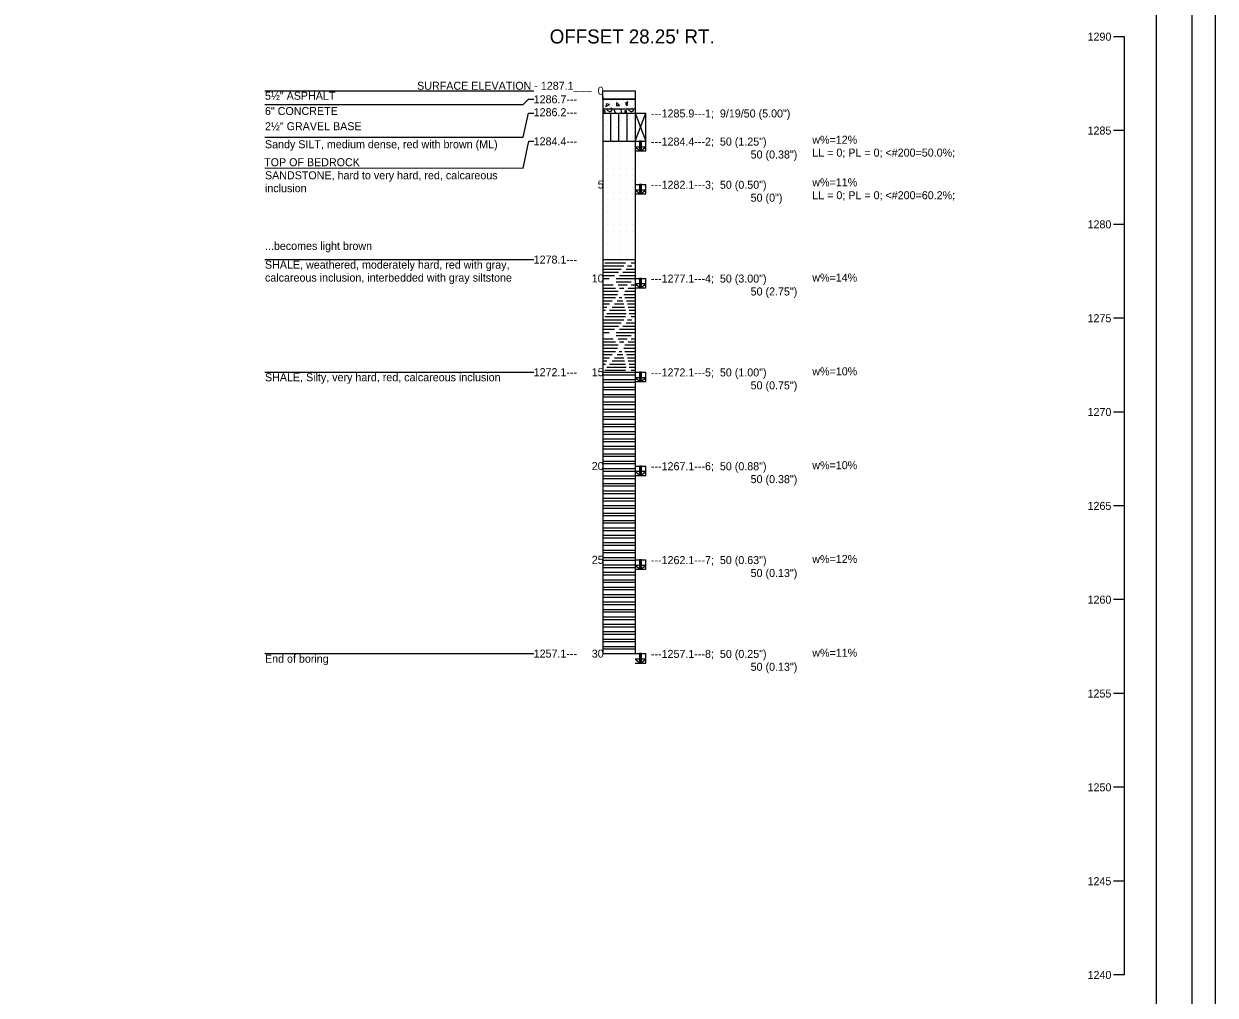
# Model space of a CAD drawing. Extents: x -6 to 173, y 24 to 64.
# Drawn here: x 107.52 to 125.98, y 35.65 to 50.69 of the extents above; entities that cross this region are included whole.
import ezdxf

# ---------------------------------------------------------------- set-up
doc = ezdxf.new("R2010")
doc.units = 0
for name, color, linetype in [('SHT_Plot_Shape_Full', 7, 'Continuous'), ('SHT_Plot_Shape_Half', 7, 'Continuous'), ('SHT_Sheet_Border', 7, 'Continuous')]:
    doc.layers.add(name, color=color, linetype=linetype)

# ---------------------------------------------------------------- blocks, each defined once
blk = doc.blocks.new('POINT_DISPLAY')
blk.add_line((0, 0), (0, 0))

msp = doc.modelspace()

# ---------------------------------------------------------------- linework, layer by layer
msp.add_line((124.573, 35.958), (124.573, 50.493))
for points in [[(124.573, 50.493), (124.406, 50.493)], [(111.26, 49.656), (115.427, 49.656)], [(111.26, 49.44), (115.26, 49.44), (115.344, 49.523), (115.427, 49.523)], [(116.493, 49.563), (116.493, 40.936)], [(116.493, 49.523), (116.993, 49.523)], [(116.753, 49.428), (116.706, 49.474), (116.706, 49.428), (116.753, 49.428)], [(116.87, 49.42), (116.882, 49.486), (116.843, 49.459), (116.87, 49.42)], [(116.993, 49.523), (116.993, 40.936)], [(111.26, 48.935), (115.26, 48.935), (115.344, 49.308), (115.427, 49.308)], [(116.493, 49.377), (116.993, 49.377)], [(116.493, 49.308), (116.993, 49.308)], [(116.506, 49.347), (116.496, 49.337), (116.499, 49.327), (116.504, 49.314), (116.515, 49.312), (116.528, 49.322), (116.528, 49.336), (116.519, 49.351), (116.506, 49.347)], [(116.539, 49.409), (116.597, 49.442), (116.551, 49.454), (116.539, 49.409)], [(116.629, 49.377), (116.629, 49.346), (116.624, 49.338), (116.609, 49.33), (116.594, 49.331), (116.584, 49.338), (116.572, 49.346), (116.561, 49.353), (116.554, 49.367), (116.554, 49.377)], [(116.626, 49.389), (116.614, 49.377), (116.626, 49.377), (116.626, 49.389)], [(116.618, 48.872), (116.618, 49.308)], [(116.7, 49.308), (116.693, 49.313), (116.681, 49.332), (116.675, 49.352), (116.674, 49.352), (116.677, 49.377)], [(116.743, 48.872), (116.743, 49.308)], [(116.769, 49.377), (116.774, 49.367), (116.774, 49.356), (116.775, 49.342), (116.778, 49.338), (116.782, 49.331), (116.777, 49.311), (116.772, 49.308)], [(116.839, 49.347), (116.829, 49.337), (116.833, 49.327), (116.838, 49.314), (116.849, 49.312), (116.861, 49.322), (116.861, 49.336), (116.853, 49.351), (116.839, 49.347)], [(116.868, 48.872), (116.868, 49.308)], [(116.962, 49.377), (116.963, 49.346), (116.957, 49.338), (116.942, 49.33), (116.928, 49.331), (116.917, 49.338), (116.905, 49.346), (116.894, 49.353), (116.888, 49.367), (116.888, 49.377)], [(116.954, 49.381), (116.94, 49.377), (116.951, 49.377), (116.954, 49.381)], [(116.993, 49.308), (117.159, 48.872)], [(116.993, 48.872), (117.159, 49.308)], [(116.993, 49.308), (117.159, 49.308)], [(117.159, 48.872), (117.159, 49.308)], [(124.573, 49.039), (124.406, 49.039)], [(111.26, 48.46), (115.26, 48.456), (115.345, 48.872), (115.427, 48.872)], [(116.493, 48.872), (116.993, 48.872)], [(116.993, 48.872), (117.159, 48.872)], [(116.993, 48.872), (117.159, 48.872)], [(116.993, 48.726), (117.159, 48.726)], [(117.159, 48.726), (117.159, 48.872)], [(116.993, 48.203), (117.159, 48.203)], [(117.159, 48.058), (117.159, 48.203)], [(116.993, 48.058), (117.159, 48.058)], [(124.573, 47.586), (124.406, 47.586)], [(111.26, 47.04), (115.427, 47.04)], [(116.493, 47.04), (116.993, 47.04)], [(116.493, 46.942), (116.819, 46.942)], [(116.493, 46.893), (116.779, 46.893)], [(116.526, 46.992), (116.844, 46.992)], [(116.558, 47.04), (116.853, 47.04)], [(116.853, 46.893), (116.983, 46.893)], [(116.876, 46.942), (116.943, 46.942)], [(116.901, 47.04), (116.993, 47.04)], [(116.934, 46.992), (116.993, 46.992)], [(116.493, 46.843), (116.738, 46.843)], [(116.493, 46.795), (116.673, 46.795)], [(116.493, 46.747), (116.591, 46.747)], [(116.698, 46.747), (116.993, 46.747)], [(116.698, 46.697), (116.934, 46.697)], [(116.754, 46.795), (116.993, 46.795)], [(116.803, 46.843), (116.993, 46.843)], [(116.993, 46.749), (117.159, 46.749)], [(117.159, 46.604), (117.159, 46.749)], [(116.493, 46.648), (116.656, 46.648)], [(116.493, 46.598), (116.689, 46.598)], [(116.493, 46.55), (116.729, 46.55)], [(116.729, 46.648), (116.868, 46.648)], [(116.754, 46.598), (116.819, 46.598)], [(116.836, 46.55), (116.993, 46.55)], [(116.884, 46.598), (116.993, 46.598)], [(116.934, 46.648), (116.993, 46.648)], [(116.993, 46.604), (117.159, 46.604)], [(116.493, 46.5), (116.721, 46.5)], [(116.493, 46.452), (116.689, 46.452)], [(116.493, 46.403), (116.639, 46.403)], [(116.493, 46.353), (116.599, 46.353)], [(116.673, 46.353), (116.819, 46.353)], [(116.713, 46.403), (116.803, 46.403)], [(116.746, 46.452), (116.786, 46.452)], [(116.819, 46.5), (116.993, 46.5)], [(116.836, 46.452), (116.993, 46.452)], [(116.861, 46.403), (116.993, 46.403)], [(116.876, 46.353), (116.993, 46.353)], [(116.493, 46.305), (116.558, 46.305)], [(116.493, 46.255), (116.534, 46.255)], [(116.526, 46.158), (116.844, 46.158)], [(116.558, 46.207), (116.853, 46.207)], [(116.599, 46.255), (116.844, 46.255)], [(116.639, 46.305), (116.828, 46.305)], [(116.884, 46.305), (116.993, 46.305)], [(116.901, 46.255), (116.993, 46.255)], [(116.901, 46.207), (116.993, 46.207)], [(116.934, 46.158), (116.993, 46.158)], [(116.493, 46.108), (116.819, 46.108)], [(116.493, 46.06), (116.779, 46.06)], [(116.493, 46.01), (116.738, 46.01)], [(116.493, 45.962), (116.673, 45.962)], [(116.754, 45.962), (116.993, 45.962)], [(116.803, 46.01), (116.993, 46.01)], [(116.853, 46.06), (116.983, 46.06)], [(116.876, 46.108), (116.943, 46.108)], [(124.573, 46.132), (124.406, 46.132)], [(116.493, 45.913), (116.591, 45.913)], [(116.493, 45.815), (116.656, 45.815)], [(116.698, 45.913), (116.993, 45.913)], [(116.698, 45.863), (116.934, 45.863)], [(116.729, 45.815), (116.868, 45.815)], [(116.934, 45.815), (116.993, 45.815)], [(116.493, 45.765), (116.689, 45.765)], [(116.493, 45.717), (116.729, 45.717)], [(116.493, 45.667), (116.721, 45.667)], [(116.493, 45.618), (116.689, 45.618)], [(116.746, 45.618), (116.786, 45.618)], [(116.754, 45.765), (116.819, 45.765)], [(116.819, 45.667), (116.993, 45.667)], [(116.836, 45.717), (116.993, 45.717)], [(116.836, 45.618), (116.993, 45.618)], [(116.884, 45.765), (116.993, 45.765)], [(116.493, 45.57), (116.639, 45.57)], [(116.493, 45.52), (116.599, 45.52)], [(116.493, 45.472), (116.558, 45.472)], [(116.493, 45.422), (116.534, 45.422)], [(116.599, 45.422), (116.844, 45.422)], [(116.639, 45.472), (116.828, 45.472)], [(116.673, 45.52), (116.819, 45.52)], [(116.713, 45.57), (116.803, 45.57)], [(116.861, 45.57), (116.993, 45.57)], [(116.876, 45.52), (116.993, 45.52)], [(116.884, 45.472), (116.993, 45.472)], [(116.901, 45.422), (116.993, 45.422)], [(111.26, 45.296), (115.427, 45.296)], [(116.493, 45.296), (116.993, 45.296)], [(116.493, 45.296), (116.993, 45.296)], [(116.493, 45.257), (116.993, 45.257)], [(116.526, 45.325), (116.844, 45.325)], [(116.558, 45.373), (116.853, 45.373)], [(116.901, 45.373), (116.993, 45.373)], [(116.934, 45.325), (116.993, 45.325)], [(116.993, 45.296), (117.159, 45.296)], [(117.159, 45.151), (117.159, 45.296)], [(116.493, 45.181), (116.993, 45.181)], [(116.493, 45.142), (116.993, 45.142)], [(116.493, 45.066), (116.993, 45.066)], [(116.993, 45.151), (117.159, 45.151)], [(116.493, 45.027), (116.993, 45.027)], [(116.493, 44.951), (116.993, 44.951)], [(116.493, 44.912), (116.993, 44.912)], [(116.493, 44.837), (116.993, 44.837)], [(116.493, 44.797), (116.993, 44.797)], [(116.493, 44.722), (116.993, 44.722)], [(116.493, 44.682), (116.993, 44.682)], [(124.573, 44.679), (124.406, 44.679)], [(116.493, 44.607), (116.993, 44.607)], [(116.493, 44.568), (116.993, 44.568)], [(116.493, 44.492), (116.993, 44.492)], [(116.493, 44.453), (116.993, 44.453)], [(116.493, 44.377), (116.993, 44.377)], [(116.493, 44.338), (116.993, 44.338)], [(116.493, 44.263), (116.993, 44.263)], [(116.493, 44.223), (116.993, 44.223)], [(116.493, 44.148), (116.993, 44.148)], [(116.493, 44.108), (116.993, 44.108)], [(116.493, 44.033), (116.993, 44.033)], [(116.493, 43.993), (116.993, 43.993)], [(116.493, 43.918), (116.993, 43.918)], [(116.493, 43.879), (116.993, 43.879)], [(116.493, 43.803), (116.993, 43.803)], [(116.493, 43.764), (116.993, 43.764)], [(116.993, 43.842), (117.159, 43.842)], [(117.159, 43.697), (117.159, 43.842)], [(116.493, 43.688), (116.993, 43.688)], [(116.493, 43.649), (116.993, 43.649)], [(116.493, 43.574), (116.993, 43.574)], [(116.993, 43.697), (117.159, 43.697)], [(116.493, 43.534), (116.993, 43.534)], [(116.493, 43.459), (116.993, 43.459)], [(116.493, 43.419), (116.993, 43.419)], [(116.493, 43.344), (116.993, 43.344)], [(116.493, 43.305), (116.993, 43.305)], [(116.493, 43.229), (116.993, 43.229)], [(116.493, 43.19), (116.993, 43.19)], [(124.573, 43.225), (124.406, 43.225)], [(116.493, 43.114), (116.993, 43.114)], [(116.493, 43.075), (116.993, 43.075)], [(116.493, 42.999), (116.993, 42.999)], [(116.493, 42.96), (116.993, 42.96)], [(116.493, 42.885), (116.993, 42.885)], [(116.493, 42.845), (116.993, 42.845)], [(116.493, 42.77), (116.993, 42.77)], [(116.493, 42.73), (116.993, 42.73)], [(116.493, 42.655), (116.993, 42.655)], [(116.493, 42.616), (116.993, 42.616)], [(116.493, 42.54), (116.993, 42.54)], [(116.493, 42.501), (116.993, 42.501)], [(116.493, 42.425), (116.993, 42.425)], [(116.493, 42.386), (116.993, 42.386)], [(116.493, 42.31), (116.993, 42.31)], [(116.493, 42.271), (116.993, 42.271)], [(116.993, 42.389), (117.159, 42.389)], [(117.159, 42.244), (117.159, 42.389)], [(116.493, 42.196), (116.993, 42.196)], [(116.493, 42.156), (116.993, 42.156)], [(116.493, 42.081), (116.993, 42.081)], [(116.993, 42.244), (117.159, 42.244)], [(116.493, 42.041), (116.993, 42.041)], [(116.493, 41.966), (116.993, 41.966)], [(116.493, 41.927), (116.993, 41.927)], [(116.493, 41.851), (116.993, 41.851)], [(116.493, 41.812), (116.993, 41.812)], [(116.493, 41.736), (116.993, 41.736)], [(124.573, 41.772), (124.406, 41.772)], [(116.493, 41.697), (116.993, 41.697)], [(116.493, 41.621), (116.993, 41.621)], [(116.493, 41.582), (116.993, 41.582)], [(116.493, 41.507), (116.993, 41.507)], [(116.493, 41.467), (116.993, 41.467)], [(116.493, 41.392), (116.993, 41.392)], [(116.493, 41.352), (116.993, 41.352)], [(116.493, 41.277), (116.993, 41.277)], [(116.493, 41.238), (116.993, 41.238)], [(116.493, 41.162), (116.993, 41.162)], [(116.493, 41.123), (116.993, 41.123)], [(116.493, 41.047), (116.993, 41.047)], [(116.493, 41.008), (116.993, 41.008)], [(111.26, 40.936), (115.427, 40.936)], [(116.493, 40.936), (116.993, 40.936)], [(116.993, 40.936), (117.159, 40.936)], [(116.993, 40.79), (117.159, 40.79)], [(117.159, 40.79), (117.159, 40.936)], [(124.573, 40.318), (124.406, 40.318)], [(124.573, 38.865), (124.406, 38.865)], [(124.573, 37.411), (124.406, 37.411)], [(124.573, 35.958), (124.406, 35.958)]]:
    msp.add_lwpolyline(points)
for points in [[(116.493, 49.523), (116.493, 49.656), (116.993, 49.656), (116.993, 49.523)], [(117.059, 48.784), (116.993, 48.784), (117.076, 48.726), (117.059, 48.784)], [(117.059, 48.784), (117.093, 48.784), (117.093, 48.872), (117.059, 48.784)], [(117.059, 48.784), (117.093, 48.872), (117.059, 48.872), (117.059, 48.784)], [(117.059, 48.784), (117.076, 48.726), (117.093, 48.784), (117.059, 48.784)], [(117.076, 48.726), (117.159, 48.784), (117.093, 48.784), (117.076, 48.726)], [(117.059, 48.116), (117.093, 48.116), (117.093, 48.203), (117.059, 48.116)], [(117.059, 48.116), (117.093, 48.203), (117.059, 48.203), (117.059, 48.116)], [(117.059, 48.116), (116.993, 48.116), (117.076, 48.058), (117.059, 48.116)], [(117.059, 48.116), (117.076, 48.058), (117.093, 48.116), (117.059, 48.116)], [(117.076, 48.058), (117.159, 48.116), (117.093, 48.116), (117.076, 48.058)], [(117.059, 46.662), (117.093, 46.662), (117.093, 46.749), (117.059, 46.662)], [(117.059, 46.662), (117.093, 46.749), (117.059, 46.749), (117.059, 46.662)], [(117.059, 46.662), (116.993, 46.662), (117.076, 46.604), (117.059, 46.662)], [(117.059, 46.662), (117.076, 46.604), (117.093, 46.662), (117.059, 46.662)], [(117.076, 46.604), (117.159, 46.662), (117.093, 46.662), (117.076, 46.604)], [(117.059, 45.209), (117.093, 45.209), (117.093, 45.296), (117.059, 45.209)], [(117.059, 45.209), (117.093, 45.296), (117.059, 45.296), (117.059, 45.209)], [(117.059, 45.209), (116.993, 45.209), (117.076, 45.151), (117.059, 45.209)], [(117.059, 45.209), (117.076, 45.151), (117.093, 45.209), (117.059, 45.209)], [(117.076, 45.151), (117.159, 45.209), (117.093, 45.209), (117.076, 45.151)], [(117.059, 43.755), (116.993, 43.755), (117.076, 43.697), (117.059, 43.755)], [(117.059, 43.755), (117.093, 43.755), (117.093, 43.842), (117.059, 43.755)], [(117.059, 43.755), (117.093, 43.842), (117.059, 43.842), (117.059, 43.755)], [(117.059, 43.755), (117.076, 43.697), (117.093, 43.755), (117.059, 43.755)], [(117.076, 43.697), (117.159, 43.755), (117.093, 43.755), (117.076, 43.697)], [(117.059, 42.302), (116.993, 42.302), (117.076, 42.244), (117.059, 42.302)], [(117.059, 42.302), (117.093, 42.302), (117.093, 42.389), (117.059, 42.302)], [(117.059, 42.302), (117.093, 42.389), (117.059, 42.389), (117.059, 42.302)], [(117.059, 42.302), (117.076, 42.244), (117.093, 42.302), (117.059, 42.302)], [(117.076, 42.244), (117.159, 42.302), (117.093, 42.302), (117.076, 42.244)], [(117.059, 40.848), (116.993, 40.848), (117.076, 40.79), (117.059, 40.848)], [(117.059, 40.848), (117.093, 40.848), (117.093, 40.936), (117.059, 40.848)], [(117.059, 40.848), (117.093, 40.936), (117.059, 40.936), (117.059, 40.848)], [(117.059, 40.848), (117.076, 40.79), (117.093, 40.848), (117.059, 40.848)], [(117.076, 40.79), (117.159, 40.848), (117.093, 40.848), (117.076, 40.79)]]:
    msp.add_lwpolyline(points, close=True)
at = {"layer": 'SHT_Plot_Shape_Full'}
msp.add_lwpolyline([(89.979, 53.971), (125.979, 53.971), (125.979, 29.971), (89.979, 29.971)], close=True, dxfattribs=at)
at = {"layer": 'SHT_Plot_Shape_Half'}
msp.add_lwpolyline([(91.616, 53.146), (125.616, 53.146), (125.616, 31.146), (91.616, 31.146)], close=True, dxfattribs=at)
at = {"layer": 'SHT_Sheet_Border'}
msp.add_lwpolyline([(93.566, 52.646), (125.066, 52.646), (125.066, 31.646), (93.566, 31.646)], close=True, dxfattribs=at)

# ---------------------------------------------------------------- block references
at = {"xscale": 0.01, "yscale": 0.01}
for p in [(116.496, 49.481), (116.512, 49.514), (116.529, 49.464), (116.546, 49.498), (116.596, 49.514), (116.607, 49.483), (116.629, 49.464), (116.646, 49.498), (116.679, 49.464), (116.706, 49.506), (116.729, 49.481), (116.762, 49.514), (116.796, 49.464), (116.812, 49.498), (116.829, 49.481), (116.846, 49.514), (116.862, 49.464), (116.879, 49.498), (116.929, 49.514), (116.94, 49.483), (116.962, 49.464), (116.979, 49.498), (116.512, 49.431), (116.529, 49.398), (116.532, 49.291), (116.562, 49.448), (116.562, 49.381), (116.596, 49.414), (116.637, 49.427), (116.646, 49.398), (116.699, 49.291), (116.705, 49.389), (116.712, 49.431), (116.75, 49.412), (116.762, 49.448), (116.762, 49.381), (116.79, 49.41), (116.812, 49.381), (116.823, 49.414), (116.846, 49.431), (116.862, 49.398), (116.896, 49.448), (116.896, 49.381), (116.918, 49.274), (116.929, 49.414), (116.971, 49.427), (116.979, 49.398), (116.499, 49.224), (116.532, 49.124), (116.565, 49.191), (116.599, 49.258), (116.632, 49.158), (116.699, 49.091), (116.722, 49.227), (116.765, 49.191), (116.782, 49.115), (116.799, 49.258), (116.865, 49.191), (116.932, 49.124), (116.965, 49.224), (116.564, 49.048), (116.564, 48.949), (116.662, 49.048), (116.662, 48.949), (116.761, 49.048), (116.761, 48.949), (116.859, 49.048), (116.859, 48.949), (116.958, 49.048), (116.958, 48.949), (116.564, 48.851), (116.564, 48.753), (116.662, 48.851), (116.662, 48.753), (116.761, 48.851), (116.761, 48.753), (116.859, 48.851), (116.859, 48.753), (116.958, 48.851), (116.958, 48.753), (116.564, 48.654), (116.564, 48.556), (116.662, 48.654), (116.662, 48.556), (116.761, 48.654), (116.761, 48.556), (116.859, 48.654), (116.859, 48.556), (116.958, 48.654), (116.958, 48.556), (116.564, 48.457), (116.564, 48.359), (116.662, 48.457), (116.662, 48.359), (116.761, 48.457), (116.761, 48.359), (116.859, 48.457), (116.859, 48.359), (116.958, 48.457), (116.958, 48.359), (116.564, 48.26), (116.662, 48.26), (116.761, 48.26), (116.859, 48.26), (116.958, 48.26), (116.564, 48.162), (116.564, 48.064), (116.662, 48.162), (116.662, 48.064), (116.761, 48.162), (116.761, 48.064), (116.859, 48.162), (116.859, 48.064), (116.958, 48.162), (116.958, 48.064), (116.564, 47.965), (116.564, 47.867), (116.662, 47.965), (116.662, 47.867), (116.761, 47.965), (116.761, 47.867), (116.859, 47.965), (116.859, 47.867), (116.958, 47.965), (116.958, 47.867), (116.564, 47.768), (116.564, 47.67), (116.662, 47.768), (116.662, 47.67), (116.761, 47.768), (116.761, 47.67), (116.859, 47.768), (116.859, 47.67), (116.958, 47.768), (116.958, 47.67), (116.564, 47.571), (116.564, 47.473), (116.662, 47.571), (116.662, 47.473), (116.761, 47.571), (116.761, 47.473), (116.859, 47.571), (116.859, 47.473), (116.958, 47.571), (116.958, 47.473), (116.564, 47.375), (116.564, 47.276), (116.662, 47.375), (116.662, 47.276), (116.761, 47.375), (116.761, 47.276), (116.859, 47.375), (116.859, 47.276), (116.958, 47.375), (116.958, 47.276), (116.564, 47.178), (116.564, 47.079), (116.662, 47.178), (116.662, 47.079), (116.761, 47.178), (116.761, 47.079), (116.859, 47.178), (116.859, 47.079), (116.958, 47.178), (116.958, 47.079)]:
    msp.add_blockref('POINT_DISPLAY', p, dxfattribs=at)

# ---------------------------------------------------------------- texts
for s, height, p in [("OFFSET 28.25' RT.", 0.217, (115.671, 50.388)), ('1290', 0.124, (124.002, 50.431)), ('SURFACE ELEVATION - 1287.1___', 0.124, (113.617, 49.671)), ('0', 0.124, (116.414, 49.594)), ('5½" ASPHALT', 0.124, (111.26, 49.516)), ('1286.7---', 0.124, (115.422, 49.461)), ('6" CONCRETE', 0.124, (111.26, 49.28)), ('1286.2---', 0.124, (115.422, 49.261)), ('---1285.9---1;  9/19/50 (5.00")', 0.124, (117.238, 49.242)), ('2½" GRAVEL BASE', 0.124, (111.26, 49.044)), ('1285', 0.124, (124.002, 48.977)), ('1284.4---', 0.124, (115.422, 48.81)), ('---1284.4---2;  50 (1.25")', 0.124, (117.238, 48.806)), ('w%=12%', 0.124, (119.738, 48.835)), ('Sandy SILT, medium dense, red with brown (ML)', 0.124, (111.26, 48.765)), ('50 (0.38")', 0.124, (118.783, 48.606)), ('LL = 0; PL = 0; <#200=50.0%;', 0.124, (119.738, 48.635)), ('TOP OF BEDROCK', 0.124, (111.247, 48.486)), ('SANDSTONE, hard to very hard, red, calcareous', 0.124, (111.26, 48.284)), ('inclusion', 0.124, (111.26, 48.084)), ('5', 0.124, (116.414, 48.141)), ('---1282.1---3;  50 (0.50")', 0.124, (117.238, 48.137)), ('w%=11%', 0.124, (119.738, 48.175)), ('50 (0")', 0.124, (118.783, 47.937)), ('LL = 0; PL = 0; <#200=60.2%;', 0.124, (119.738, 47.975)), ('1280', 0.124, (124.002, 47.524)), ('...becomes light brown', 0.124, (111.26, 47.19)), ('1278.1---', 0.124, (115.422, 46.978)), ('SHALE, weathered, moderately hard, red with gray,', 0.124, (111.26, 46.899)), ('calcareous inclusion, interbedded with gray siltstone', 0.124, (111.26, 46.699)), ('10', 0.124, (116.322, 46.687)), ('---1277.1---4;  50 (3.00")', 0.124, (117.238, 46.684)), ('w%=14%', 0.124, (119.738, 46.7)), ('50 (2.75")', 0.124, (118.783, 46.484)), ('1275', 0.124, (124.002, 46.07)), ('SHALE, Silty, very hard, red, calcareous inclusion', 0.124, (111.26, 45.155)), ('1272.1---', 0.124, (115.422, 45.234)), ('15', 0.124, (116.322, 45.234)), ('---1272.1---5;  50 (1.00")', 0.124, (117.238, 45.23)), ('w%=10%', 0.124, (119.738, 45.247)), ('50 (0.75")', 0.124, (118.783, 45.03)), ('1270', 0.124, (124.002, 44.617)), ('20', 0.124, (116.322, 43.78)), ('---1267.1---6;  50 (0.88")', 0.124, (117.238, 43.777)), ('w%=10%', 0.124, (119.738, 43.793)), ('50 (0.38")', 0.124, (118.783, 43.577)), ('1265', 0.124, (124.002, 43.163)), ('25', 0.124, (116.322, 42.327)), ('---1262.1---7;  50 (0.63")', 0.124, (117.238, 42.323)), ('w%=12%', 0.124, (119.738, 42.34)), ('50 (0.13")', 0.124, (118.783, 42.123)), ('1260', 0.124, (124.002, 41.71)), ('1257.1---', 0.124, (115.422, 40.874)), ('30', 0.124, (116.322, 40.874)), ('---1257.1---8;  50 (0.25")', 0.124, (117.238, 40.87)), ('w%=11%', 0.124, (119.738, 40.887)), ('End of boring', 0.124, (111.26, 40.795)), ('50 (0.13")', 0.124, (118.783, 40.67)), ('1255', 0.124, (124.002, 40.256)), ('1250', 0.124, (124.002, 38.803)), ('1245', 0.124, (124.002, 37.349)), ('1240', 0.124, (124.002, 35.896))]:
    msp.add_text(s, height=height).set_placement(p)

doc.saveas('drawing.dxf')
